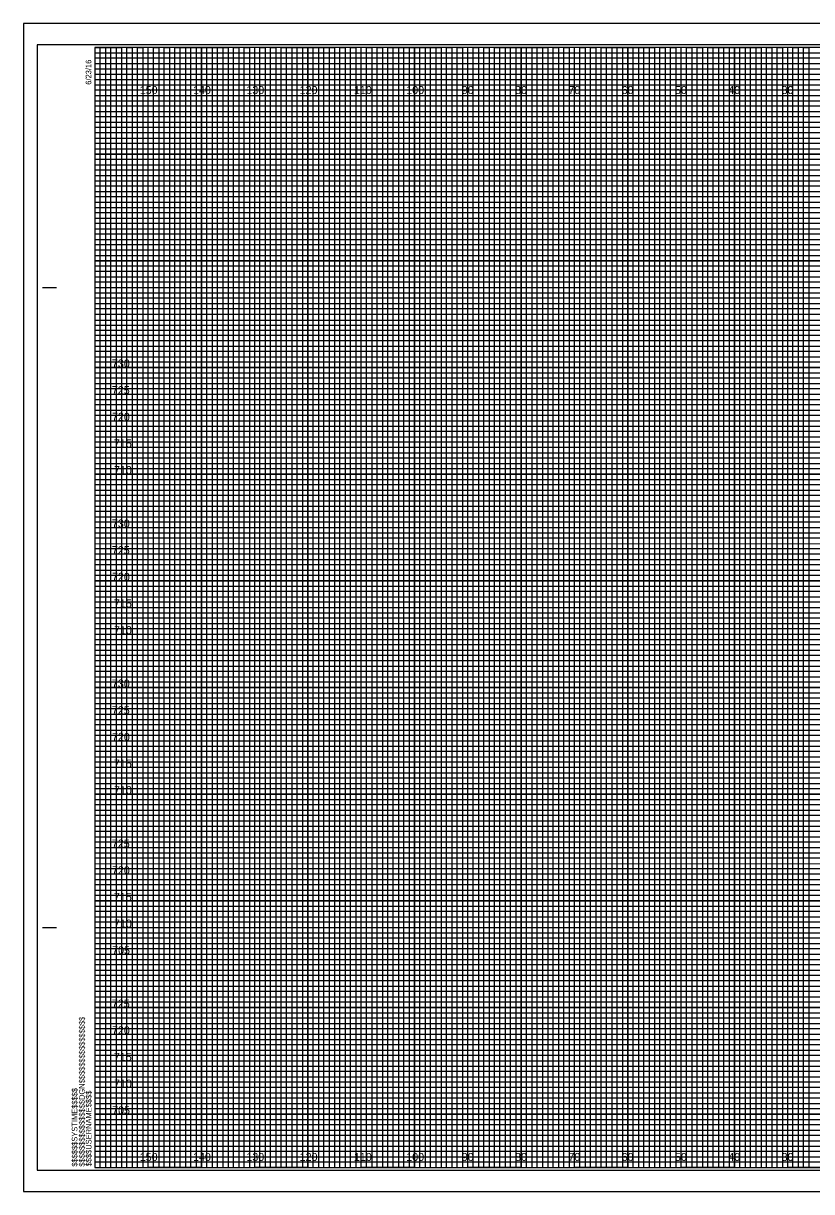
# Model space of a CAD drawing. Extents: x -13 to 323, y -5 to 434.
# Drawn here: x -13.4 to 134.5, y 215.5 to 434.5 of the extents above; entities that cross this region are included whole.
import ezdxf

# ---------------------------------------------------------------- set-up
doc = ezdxf.new("R2010")
doc.units = 0
for name, color, linetype in [('Exist Cross Section Cell', 7, 'Continuous'), ('Prop CMT Pvmt Course 1', 7, 'Continuous'), ('Prop CMT Pvmt Course 2', 7, 'Continuous'), ('Prop CMT Pvmt Course 3', 7, 'Continuous'), ('Prop CMT Pvmt Surface Shoulder', 7, 'Continuous'), ('Prop CMT Shld Paved Course 1', 7, 'Continuous'), ('Prop CMT Shld Paved Course 2', 7, 'Continuous'), ('Prop CMT Shld Paved Course 3', 7, 'Continuous'), ('Prop CMT Slope Grass', 7, 'Continuous'), ('Prop CMT Subgrade Earthwork', 7, 'Continuous'), ('Scratch_Level_1', 7, 'Continuous')]:
    doc.layers.add(name, color=color, linetype=linetype)

msp = doc.modelspace()

# ---------------------------------------------------------------- linework, layer by layer
at = {"layer": 'Prop CMT Pvmt Course 1'}
msp.add_lwpolyline([(-10.8, 219.5), (322.4, 219.5), (322.4, 430.5), (-10.8, 430.5)], close=True, dxfattribs=at)
at = {"layer": 'Prop CMT Pvmt Course 2'}
for p, q in [((10, 220), (10, 430)), ((20, 220), (20, 430)), ((30, 220), (30, 430)), ((40, 220), (40, 430)), ((50, 220), (50, 430)), ((60, 220), (60, 430)), ((70, 220), (70, 430)), ((80, 220), (80, 430)), ((90, 220), (90, 430)), ((100, 220), (100, 430)), ((110, 220), (110, 430)), ((120, 220), (120, 430)), ((130, 220), (130, 430)), ((0, 420), (320, 420)), ((0, 410), (320, 410)), ((0, 400), (320, 400)), ((0, 390), (320, 390)), ((0, 380), (320, 380)), ((0, 370), (320, 370)), ((0, 360), (320, 360)), ((0, 350), (320, 350)), ((0, 340), (320, 340)), ((0, 330), (320, 330)), ((0, 320), (320, 320)), ((0, 310), (320, 310)), ((0, 300), (320, 300)), ((0, 290), (320, 290)), ((0, 280), (320, 280)), ((0, 270), (320, 270)), ((0, 260), (320, 260)), ((0, 250), (320, 250)), ((0, 240), (320, 240)), ((0, 230), (320, 230))]:
    msp.add_line(p, q, dxfattribs=at)
at = {"layer": 'Prop CMT Pvmt Course 3'}
for p, q in [((323.3, 434.5), (-13.4, 434.5)), ((-13.4, 434.5), (-13.4, 215.5)), ((-13.4, 215.5), (323.3, 215.5))]:
    msp.add_line(p, q, dxfattribs=at)
at = {"layer": 'Prop CMT Pvmt Surface Shoulder'}
msp.add_lwpolyline([(-13.4, 215.5), (323.3, 215.5), (323.3, 434.5), (-13.4, 434.5)], close=True, dxfattribs=at)
at = {"layer": 'Prop CMT Shld Paved Course 1'}
for points in [[(0, 430), (5, 430), (5, 220), (15, 220), (15, 430), (25, 430), (25, 220), (35, 220), (35, 430), (45, 430), (45, 220), (55, 220), (55, 430), (65, 430), (65, 220), (75, 220), (75, 430), (85, 430), (85, 220), (95, 220), (95, 430), (105, 430), (105, 220), (115, 220), (115, 430), (125, 430), (125, 220), (135, 220)], [(0, 425), (275, 425)], [(0, 405), (320, 405), (320, 415), (0, 415)], [(0, 385), (320, 385), (320, 395), (0, 395)], [(0, 365), (320, 365), (320, 375), (0, 375)], [(0, 345), (320, 345), (320, 355), (0, 355)], [(0, 325), (320, 325), (320, 335), (0, 335)], [(0, 305), (320, 305), (320, 315), (0, 315)], [(0, 285), (320, 285), (320, 295), (0, 295)], [(0, 265), (320, 265), (320, 275), (0, 275)], [(0, 245), (320, 245), (320, 255), (0, 255)], [(0, 225), (320, 225), (320, 235), (0, 235)]]:
    msp.add_lwpolyline(points, dxfattribs=at)
at = {"layer": 'Prop CMT Shld Paved Course 2'}
for p, q in [((0, 429), (260, 429)), ((260, 427.98), (0, 427.98)), ((0, 427.98), (0, 427)), ((0, 427), (260, 427)), ((260, 425.89), (0, 425.89)), ((0, 425.89), (0, 424)), ((0, 424), (320, 424))]:
    msp.add_line(p, q, dxfattribs=at)
for points in [[(0, 423), (270, 423), (320, 423), (320, 422), (0, 422)], [(0, 421), (320, 421), (320, 419), (0, 419)], [(0, 418), (320, 418), (320, 417), (0, 416.98)], [(0, 416), (320, 416), (320, 414), (0, 414)], [(0, 413), (320, 413), (320, 412), (0, 412)], [(0, 411), (320, 411), (320, 409), (0, 409)], [(0, 408), (320, 408), (320, 407), (0, 407)], [(0, 406), (320, 406), (320, 404), (0, 404)], [(0, 403), (320, 403), (320, 402), (0, 402)], [(0, 401), (320, 401), (320, 399), (0, 399)], [(0, 398), (320, 398), (320, 397), (0, 397)], [(0, 396), (320, 396), (320, 393.95), (320, 393), (320, 392), (0, 392)], [(0, 394), (320, 394), (320, 393), (0, 393)], [(0, 391), (320, 391), (320, 389), (0, 389.03)], [(0, 389.03), (320, 389), (320, 388), (0, 388)], [(0, 387), (320, 387), (320, 386), (0, 386)], [(0, 384), (320, 384), (320, 383), (0, 383)], [(0, 382), (320, 382), (320, 381), (0, 381)], [(-0.07, 378.89), (320, 378.89), (320, 377.88), (-0.07, 377.88)], [(0, 377), (320, 377), (320, 376), (0, 376)], [(0, 374), (320, 374), (320, 373), (0, 373)], [(0, 372), (320, 372), (320, 371), (0, 371)], [(0, 369), (320, 369), (320, 368), (0, 368)], [(0, 367), (320, 367), (320, 366), (0, 366)], [(0, 364), (320, 364), (320, 363), (0, 363)], [(0, 362), (320, 362), (320, 361), (0, 361)], [(0, 359), (320, 359), (319.99, 357.98), (0, 358)], [(0, 357), (320, 357), (320, 356), (0, 356)], [(0, 354), (320, 354), (320, 353), (0, 353)], [(0, 352), (320, 352), (320, 351), (0, 351)], [(0, 349), (320, 349), (320, 348), (0, 348)], [(0, 347), (320, 347), (320, 346), (0, 346)], [(0, 344), (320, 344), (320, 343), (0, 343)], [(0, 342), (320, 342), (320, 341), (0, 341)], [(0, 339), (320, 339), (320, 338), (0, 338)], [(0, 336.99), (320.07, 336.91), (320, 336), (0, 336)], [(0, 334), (320, 334), (320, 333), (0, 333)], [(0, 332), (320, 332), (320, 331), (0, 331)], [(0, 329), (320, 329), (320, 328), (0, 328)], [(0, 327), (320, 327), (320, 326), (0, 326)], [(0, 324), (320, 324), (320, 323), (0, 323)], [(0, 322), (320, 322), (320, 321), (0, 321)], [(0, 319), (320, 319), (320, 318), (0, 318)], [(0, 317), (320, 317), (320, 316), (0, 316)], [(0, 314), (320, 314), (320, 313), (0, 313)], [(0, 312), (320, 312), (320, 311), (0, 311)], [(0, 309), (320, 309), (320, 308), (0, 308)], [(0, 307), (320, 307), (320, 306), (0, 306)], [(0, 304), (320, 304), (320, 303), (0, 303)], [(0, 302), (320, 302), (320, 301), (0, 301)], [(0, 299), (320, 299), (319.99, 297.98), (0, 298)], [(0, 297), (320, 297), (320, 296), (0, 296)], [(0, 294), (320, 294), (320, 293), (0, 293)], [(0, 292), (320, 292), (320, 291), (0, 291)], [(0, 289), (320, 289), (320, 288), (0, 288)], [(0, 287), (320, 287), (320, 286), (0, 286)], [(0, 284), (320, 284), (320, 283), (0, 283)], [(0, 282), (320, 282), (320, 281), (0, 281)], [(0, 279), (320, 279), (320, 278), (0, 278)], [(0, 276.99), (320.07, 276.91), (320, 276), (0, 276)], [(0, 274), (320, 274), (320, 273), (0, 273)], [(0, 272), (320, 272), (320, 271), (0, 271)], [(0, 269), (320, 269), (320, 268), (0, 268)], [(0, 267), (320, 267), (320, 266), (0, 266)], [(0, 264), (320, 264), (320, 263), (0, 263)], [(0, 262), (320, 262), (320, 261), (0, 261)], [(0, 259), (320, 259), (320, 258), (0, 258)], [(0, 257), (320, 257), (320, 256), (0, 256)], [(0, 254), (320, 254), (320, 253), (0, 253)], [(0, 252), (320, 252), (320, 251), (0, 251)], [(0, 249), (320, 249), (320, 248), (0, 248)], [(0, 247), (320, 247), (320, 246), (0, 246)], [(0, 244), (320, 244), (320, 243), (0, 243)], [(0, 242), (320, 242), (320, 241), (0, 241)], [(0, 239), (320, 239), (320, 238), (0, 238)], [(0, 237), (320, 237), (320, 236), (0, 236)], [(0, 234), (320, 234), (320, 233), (0, 233)], [(0, 232), (320, 232), (320, 231), (0, 231)], [(0, 229), (320, 229), (320, 228), (0, 228)], [(0, 227), (320, 227), (320, 226), (0, 226)], [(0, 224), (320, 224), (320, 223), (0, 223)], [(0, 222), (320, 222), (320, 221), (0, 221)]]:
    msp.add_lwpolyline(points, dxfattribs=at)
at = {"layer": 'Prop CMT Shld Paved Course 3'}
for p, q in [((-9.8, 385), (-7.3, 385)), ((-9.7, 385), (-7.2, 385)), ((-9.8, 265), (-7.3, 265)), ((-9.7, 265), (-7.2, 265)), ((0, 220), (0, 220)), ((0, 220), (0, 220)), ((0, 220), (0, 220)), ((0, 220), (0, 220)), ((0, 220), (0, 220)), ((0, 220), (0, 220)), ((0, 220), (0, 220))]:
    msp.add_line(p, q, dxfattribs=at)
msp.add_lwpolyline([(320, 430), (0, 430), (0, 220), (320, 220)], close=True, dxfattribs=at)
at = {"layer": 'Prop CMT Subgrade Earthwork'}
for points in [[(0, 220), (1, 220), (1, 430), (2, 430), (2, 220)], [(2, 220), (3, 220), (3, 430), (4, 430), (4, 220)], [(5, 220), (6, 220), (6, 430), (7, 430), (7, 220)], [(7, 220), (8, 220), (8, 430), (9, 430), (9, 220)], [(10, 220), (11, 220), (11, 430), (12, 430), (12, 220)], [(12, 220), (13, 220), (13, 430), (14, 430), (14, 220)], [(15, 220), (16, 220), (16, 430), (17, 430), (17, 220)], [(17, 220), (18, 220), (18, 430), (19, 430), (19, 220)], [(20, 220), (21, 220), (21, 430), (22, 430), (22, 220)], [(22, 220), (23, 220), (23, 430), (24, 430), (24, 220)], [(25, 220), (26, 220), (26, 430), (27, 430), (27, 220)], [(27, 220), (28, 220), (28, 430), (29, 430), (29, 220)], [(30, 220), (31, 220), (31, 430), (32, 430), (32, 220)], [(32, 220), (33, 220), (33, 430), (34, 430), (34, 220)], [(35, 220), (36, 220), (36, 430), (37, 430), (37, 220)], [(37, 220), (38, 220), (38, 430), (39, 430), (39, 220)], [(40, 220), (41, 220), (41, 430), (42, 430), (42, 220)], [(42, 220), (43, 220), (43, 430), (44, 430), (44, 220)], [(45, 220), (46, 220), (46, 430), (47, 430), (47, 220)], [(47, 220), (48, 220), (48, 430), (49, 430), (49, 220)], [(50, 220), (51, 220), (51, 430), (52, 430), (52, 220)], [(52, 220), (53, 220), (53, 430), (54, 430), (54, 220)], [(55, 220), (56, 220), (56, 430), (57, 430), (57, 220)], [(57, 220), (58, 220), (58, 430), (59, 430), (59, 220)], [(60, 220), (61, 220), (61, 430), (62, 430), (62, 220)], [(62, 220), (63, 220), (63, 430), (64, 430), (64, 220)], [(65, 220), (66, 220), (66, 430), (67, 430), (67, 220)], [(67, 220), (68, 220), (68, 430), (69, 430), (69, 220)], [(70, 220), (71, 220), (71, 430), (72, 430), (72, 220)], [(72, 220), (73, 220), (73, 430), (74, 430), (74, 220)], [(75, 220), (76, 220), (76, 430), (77, 430), (77, 220)], [(77, 220), (78, 220), (78, 430), (79, 430), (79, 220)], [(80, 220), (81, 220), (81, 430), (82, 430), (82, 220)], [(82, 220), (83, 220), (83, 430), (84, 430), (84, 220)], [(85, 220), (86, 220), (86, 430), (87, 430), (87, 220)], [(87, 220), (88, 220), (88, 430), (89, 430), (89, 220)], [(90, 220), (91, 220), (91, 430), (92, 430), (92, 220)], [(92, 220), (93, 220), (93, 430), (94, 430), (94, 220)], [(95, 220), (96, 220), (96, 430), (97, 430), (97, 220)], [(97, 220), (98, 220), (98, 430), (99, 430), (99, 220)], [(100, 220), (101, 220), (101, 430), (102, 430), (102, 220)], [(102, 220), (103, 220), (103, 430), (104, 430), (104, 220)], [(105, 220), (106, 220), (106, 430), (107, 430), (107, 220)], [(107, 220), (108, 220), (108, 430), (109, 430), (109, 220)], [(110, 220), (111, 220), (111, 430), (112, 430), (112, 220)], [(112, 220), (113, 220), (113, 430), (114, 430), (114, 220)], [(115, 220), (116, 220), (116, 430), (117, 430), (117, 220)], [(117, 220), (118, 220), (118, 430), (119, 430), (119, 220)], [(120, 220), (121, 220), (121, 430), (122, 430), (122, 220)], [(122, 220), (123, 220), (123, 430), (124, 430), (124, 220)], [(125, 220), (126, 220), (126, 430), (127, 430), (127, 220)], [(127, 220), (128, 220), (128, 430), (129, 430), (129, 220)], [(130, 220), (131, 220), (131, 430), (132, 430), (132, 220)], [(132, 220), (133, 220), (133, 430), (134, 430), (134, 220)]]:
    msp.add_lwpolyline(points, dxfattribs=at)
at = {"layer": 'Scratch_Level_1'}
for p, q in [((10, 430), (0, 430)), ((10, 220), (10, 430)), ((30, 430), (20, 430)), ((20, 430), (20, 220)), ((30, 220), (30, 430)), ((50, 430), (40, 430)), ((40, 430), (40, 220)), ((50, 220), (50, 430)), ((70, 430), (60, 430)), ((60, 430), (60, 220)), ((70, 220), (70, 430)), ((90, 430), (80, 430)), ((80, 430), (80, 220)), ((90, 220), (90, 430)), ((110, 430), (100, 430)), ((100, 430), (100, 220)), ((110, 220), (110, 430)), ((130, 430), (120, 430)), ((120, 430), (120, 220)), ((130, 220), (130, 430)), ((20, 220), (10, 220)), ((40, 220), (30, 220)), ((60, 220), (50, 220)), ((80, 220), (70, 220)), ((100, 220), (90, 220)), ((120, 220), (110, 220)), ((140, 220), (130, 220))]:
    msp.add_line(p, q, dxfattribs=at)
for points in [[(0, 420), (320, 420), (320, 410), (0, 410)], [(0, 400), (320, 400), (320, 390), (0, 390)], [(0, 380), (320, 380), (320, 370), (0, 370)], [(0, 360), (320, 360), (320, 350), (0, 350)], [(0, 340), (320, 340), (320, 330), (0, 330)], [(0, 320), (320, 320), (320, 310), (0, 310)], [(0, 300), (320, 300), (320, 290), (0, 290)], [(0, 280), (320, 280), (320, 270), (0, 270)], [(0, 260), (320, 260), (320, 250), (0, 250)], [(0, 240), (320, 240), (320, 230), (0, 230)]]:
    msp.add_lwpolyline(points, dxfattribs=at)

# ---------------------------------------------------------------- texts
at = {"layer": 'Exist Cross Section Cell'}
for s, p in [('150', (8.44, 421.25)), ('140', (18.44, 421.25)), ('130', (28.44, 421.25)), ('120', (38.44, 421.25)), ('110', (48.62, 421.25)), ('100', (58.44, 421.25)), ('90', (68.86, 421.25)), ('80', (78.86, 421.25)), ('70', (88.86, 421.25)), ('60', (98.86, 421.25)), ('50', (108.86, 421.25)), ('40', (118.86, 421.25)), ('30', (128.86, 421.25)), ('150', (8.44, 221.25)), ('140', (18.44, 221.25)), ('130', (28.44, 221.25)), ('120', (38.44, 221.25)), ('110', (48.62, 221.25)), ('100', (58.44, 221.25)), ('90', (68.86, 221.25)), ('80', (78.86, 221.25)), ('70', (88.86, 221.25)), ('60', (98.86, 221.25)), ('50', (108.86, 221.25)), ('40', (118.86, 221.25)), ('30', (128.86, 221.25))]:
    msp.add_text(s, height=1.5, dxfattribs=at).set_placement(p)
at = {"layer": 'Prop CMT Shld Paved Course 3'}
for s, p in [('6/23/16', (-0.65, 423)), ('$$$$$$$$$$$$$$$$DGN$$$$$$$$$$$$$$$$', (-1.88, 220.18)), ('$$$$$$SYSTIME$$$$$', (-3.26, 220.18)), ('$$$$USERNAME$$$$', (-0.62, 220.23))]:
    msp.add_text(s, height=1.05, rotation=90, dxfattribs=at).set_placement(p)
at = {"layer": 'Prop CMT Slope Grass'}
for s, p in [('730', (3.22, 370)), ('725', (3.21, 365)), ('720', (3.23, 360)), ('715', (3.59, 355)), ('710', (3.61, 350)), ('730', (3.22, 340)), ('725', (3.21, 335)), ('720', (3.23, 330)), ('715', (3.59, 325)), ('710', (3.61, 320)), ('730', (3.22, 310)), ('725', (3.21, 305)), ('720', (3.23, 300)), ('715', (3.59, 295)), ('710', (3.61, 290)), ('725', (3.21, 280)), ('720', (3.23, 275)), ('715', (3.59, 270)), ('710', (3.61, 265)), ('705', (3.26, 260)), ('725', (3.21, 250)), ('720', (3.23, 245)), ('715', (3.59, 240)), ('710', (3.61, 235)), ('705', (3.26, 230))]:
    msp.add_text(s, height=1.5, dxfattribs=at).set_placement(p)

doc.saveas('drawing.dxf')
